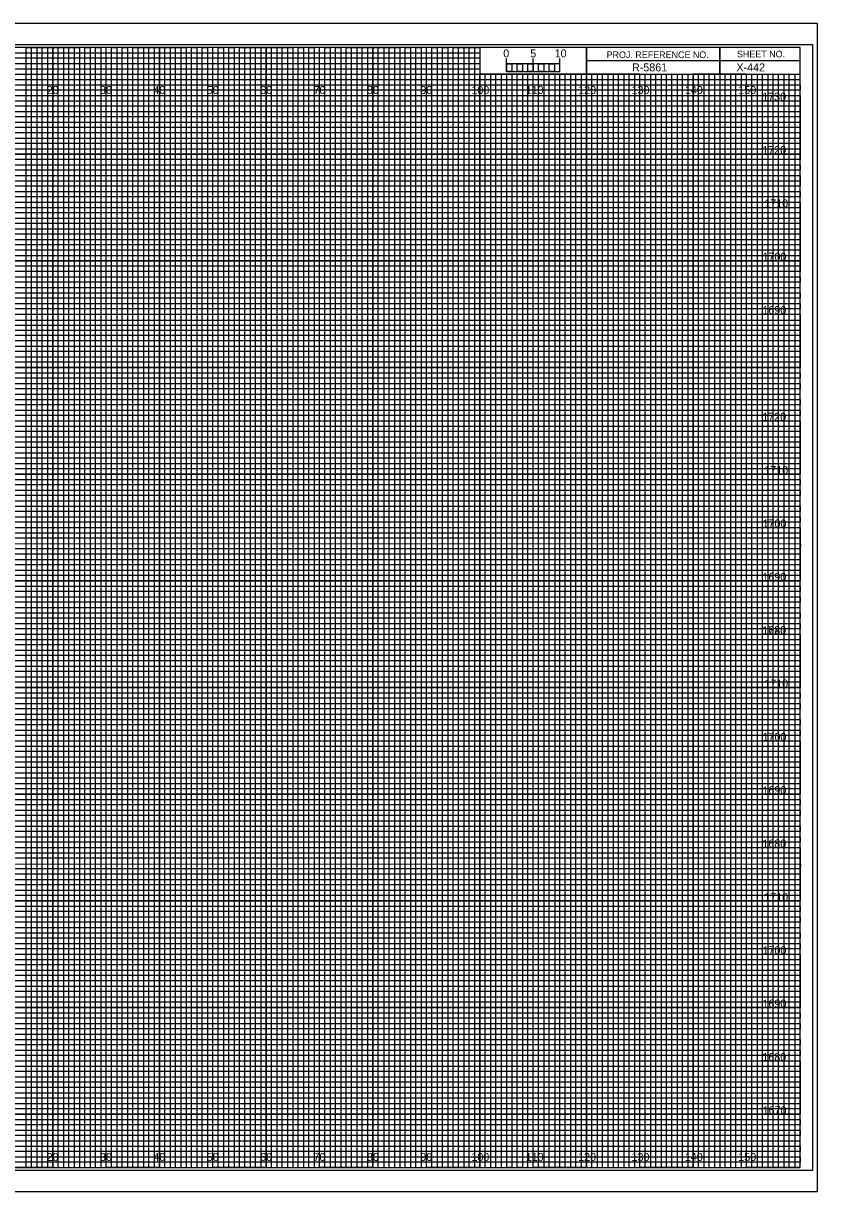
# Model space of a CAD drawing. Extents: x -13 to 323, y -5 to 1314.
# Drawn here: x 174.5 to 323.3, y 215.5 to 434.5 of the extents above; entities that cross this region are included whole.
import ezdxf

# ---------------------------------------------------------------- set-up
doc = ezdxf.new("R2010")
doc.units = 0
for name, color, linetype in [('Prop XS Bar Scale Labels', 7, 'Continuous'), ('Prop XS Project Number', 7, 'Continuous'), ('Prop XS Sheet Number', 7, 'Continuous'), ('Raster_Level_0', 7, 'Continuous'), ('Scratch_Level_3', 7, 'Continuous'), ('Sheet Cross Section CELL', 7, 'Continuous'), ('Sheet Cross Section Grid Major CELL', 7, 'Continuous'), ('Sheet Cross Section Grid Middle CELL', 7, 'Continuous'), ('Sheet Cross Section Grid Minor 1 CELL', 7, 'Continuous'), ('Sheet Cross Section Grid Minor 2 CELL', 7, 'Continuous'), ('Sheet Cross Section Scale CELL', 7, 'Continuous'), ('Sheet Cutting Line CELL', 7, 'Continuous'), ('Sheet DOT Grid CELL', 7, 'Continuous'), ('Sheet Plot Border Inside CELL', 7, 'Continuous'), ('Sheet Plot Border Outside CELL', 7, 'Continuous')]:
    doc.layers.add(name, color=color, linetype=linetype)

msp = doc.modelspace()

# ---------------------------------------------------------------- linework, layer by layer
at = {"layer": 'Sheet Cross Section CELL'}
for p, q in [((305, 430), (305, 425)), ((305, 425), (305, 430)), ((280, 427.5), (280, 425)), ((320, 427.49), (280, 427.49)), ((280, 425), (320, 425))]:
    msp.add_line(p, q, dxfattribs=at)
for points in [[(320, 430), (0, 430), (0, 220), (320, 220)], [(280, 430), (260, 430), (260, 425.03), (280, 425.03)], [(320, 430), (280, 430), (280, 425), (320, 425)]]:
    msp.add_lwpolyline(points, close=True, dxfattribs=at)
at = {"layer": 'Sheet Cross Section Grid Major CELL'}
for p, q in [((190, 430), (180, 430)), ((180, 430), (180, 220)), ((190, 220), (190, 430)), ((210, 430), (200, 430)), ((200, 430), (200, 220)), ((210, 220), (210, 430)), ((230, 430), (220, 430)), ((220, 430), (220, 220)), ((230, 220), (230, 430)), ((250, 430), (240, 430)), ((240, 430), (240, 220)), ((250, 220), (250, 430)), ((260, 430), (260, 220)), ((270, 220), (270, 425)), ((290, 425), (280, 425)), ((280, 425), (280, 220)), ((290, 220), (290, 425)), ((310, 425), (300, 425)), ((300, 425), (300, 220)), ((310, 220), (310, 425)), ((180, 220), (170, 220)), ((200, 220), (190, 220)), ((220, 220), (210, 220)), ((240, 220), (230, 220)), ((260, 220), (250, 220)), ((280, 220), (270, 220)), ((300, 220), (290, 220)), ((320, 220), (310, 220)), ((320, 220), (320, 220))]:
    msp.add_line(p, q, dxfattribs=at)
for points in [[(0, 420), (320, 420), (320, 410), (0, 410)], [(0, 400), (320, 400), (320, 390), (0, 390)], [(0, 380), (320, 380), (320, 370), (0, 370)], [(0, 360), (320, 360), (320, 350), (0, 350)], [(0, 340), (320, 340), (320, 330), (0, 330)], [(0, 320), (320, 320), (320, 310), (0, 310)], [(0, 300), (320, 300), (320, 290), (0, 290)], [(0, 280), (320, 280), (320, 270), (0, 270)], [(0, 260), (320, 260), (320, 250), (0, 250)], [(0, 240), (320, 240), (320, 230), (0, 230)]]:
    msp.add_lwpolyline(points, dxfattribs=at)
at = {"layer": 'Sheet Cross Section Grid Middle CELL'}
for points in [[(165, 220), (175, 220), (175, 430), (185, 430), (185, 220), (195, 220), (195, 430), (205, 430), (205, 220), (215, 220), (215, 430), (225, 430), (225, 220), (235, 220), (235, 430), (245, 430), (245, 220), (255, 220), (255, 430), (259.93, 430), (260, 430), (260, 425), (264.99, 425), (264.99, 220), (275, 220), (275, 425), (285, 425), (285, 220), (295, 220), (295, 425), (305, 425), (305, 220), (315, 220), (315, 425)], [(0, 425), (275, 425)], [(0, 405), (320, 405), (320, 415), (0, 415)], [(0, 385), (320, 385), (320, 395), (0, 395)], [(0, 365), (320, 365), (320, 375), (0, 375)], [(0, 345), (320, 345), (320, 355), (0, 355)], [(0, 325), (320, 325), (320, 335), (0, 335)], [(0, 305), (320, 305), (320, 315), (0, 315)], [(0, 285), (320, 285), (320, 295), (0, 295)], [(0, 265), (320, 265), (320, 275), (0, 275)], [(0, 245), (320, 245), (320, 255), (0, 255)], [(0, 225), (320, 225), (320, 235), (0, 235)]]:
    msp.add_lwpolyline(points, dxfattribs=at)
at = {"layer": 'Sheet Cross Section Grid Minor 1 CELL'}
for p, q in [((0, 429), (260, 429)), ((260, 427.98), (0, 427.98)), ((260, 429), (260, 427.98)), ((0, 427), (260, 427)), ((260, 425.89), (0, 425.89)), ((260, 427), (260, 425.89)), ((0, 424), (320, 424))]:
    msp.add_line(p, q, dxfattribs=at)
for points in [[(0, 423), (270, 423), (320, 423), (320, 422), (0, 422)], [(0, 421), (320, 421), (320, 419), (0, 419)], [(0, 418), (320, 418), (320, 417), (0, 416.98)], [(0, 416), (320, 416), (320, 414), (0, 414)], [(0, 413), (320, 413), (320, 412), (0, 412)], [(0, 411), (320, 411), (320, 409), (0, 409)], [(0, 408), (320, 408), (320, 407), (0, 407)], [(0, 406), (320, 406), (320, 404), (0, 404)], [(0, 403), (320, 403), (320, 402), (0, 402)], [(0, 401), (320, 401), (320, 399), (0, 399)], [(0, 398), (320, 398), (320, 397), (0, 397)], [(0, 396), (320, 396), (320, 393.95), (320, 393), (320, 392), (0, 392)], [(0, 394), (320, 394), (320, 393), (0, 393)], [(0, 391), (320, 391), (320, 389), (0, 389.03)], [(0, 389.03), (320, 389), (320, 388), (0, 388)], [(0, 387), (320, 387), (320, 386), (0, 386)], [(0, 384), (320, 384), (320, 383), (0, 383)], [(0, 382), (320, 382), (320, 381), (0, 381)], [(-0.07, 378.89), (320, 378.89), (320, 377.88), (-0.07, 377.88)], [(0, 377), (320, 377), (320, 376), (0, 376)], [(0, 374), (320, 374), (320, 373), (0, 373)], [(0, 372), (320, 372), (320, 371), (0, 371)], [(0, 369), (320, 369), (320, 368), (0, 368)], [(0, 367), (320, 367), (320, 366), (0, 366)], [(0, 364), (320, 364), (320, 363), (0, 363)], [(0, 362), (320, 362), (320, 361), (0, 361)], [(0, 359), (320, 359), (319.99, 357.98), (0, 358)], [(0, 357), (320, 357), (320, 356), (0, 356)], [(0, 354), (320, 354), (320, 353), (0, 353)], [(0, 352), (320, 352), (320, 351), (0, 351)], [(0, 349), (320, 349), (320, 348), (0, 348)], [(0, 347), (320, 347), (320, 346), (0, 346)], [(0, 344), (320, 344), (320, 343), (0, 343)], [(0, 342), (320, 342), (320, 341), (0, 341)], [(0, 339), (320, 339), (320, 338), (0, 338)], [(0, 336.99), (320.07, 336.91), (320, 336), (0, 336)], [(0, 334), (320, 334), (320, 333), (0, 333)], [(0, 332), (320, 332), (320, 331), (0, 331)], [(0, 329), (320, 329), (320, 328), (0, 328)], [(0, 327), (320, 327), (320, 326), (0, 326)], [(0, 324), (320, 324), (320, 323), (0, 323)], [(0, 322), (320, 322), (320, 321), (0, 321)], [(0, 319), (320, 319), (320, 318), (0, 318)], [(0, 317), (320, 317), (320, 316), (0, 316)], [(0, 314), (320, 314), (320, 313), (0, 313)], [(0, 312), (320, 312), (320, 311), (0, 311)], [(0, 309), (320, 309), (320, 308), (0, 308)], [(0, 307), (320, 307), (320, 306), (0, 306)], [(0, 304), (320, 304), (320, 303), (0, 303)], [(0, 302), (320, 302), (320, 301), (0, 301)], [(0, 299), (320, 299), (319.99, 297.98), (0, 298)], [(0, 297), (320, 297), (320, 296), (0, 296)], [(0, 294), (320, 294), (320, 293), (0, 293)], [(0, 292), (320, 292), (320, 291), (0, 291)], [(0, 289), (320, 289), (320, 288), (0, 288)], [(0, 287), (320, 287), (320, 286), (0, 286)], [(0, 284), (320, 284), (320, 283), (0, 283)], [(0, 282), (320, 282), (320, 281), (0, 281)], [(0, 279), (320, 279), (320, 278), (0, 278)], [(0, 276.99), (320.07, 276.91), (320, 276), (0, 276)], [(0, 274), (320, 274), (320, 273), (0, 273)], [(0, 272), (320, 272), (320, 271), (0, 271)], [(0, 269), (320, 269), (320, 268), (0, 268)], [(0, 267), (320, 267), (320, 266), (0, 266)], [(0, 264), (320, 264), (320, 263), (0, 263)], [(0, 262), (320, 262), (320, 261), (0, 261)], [(0, 259), (320, 259), (320, 258), (0, 258)], [(0, 257), (320, 257), (320, 256), (0, 256)], [(0, 254), (320, 254), (320, 253), (0, 253)], [(0, 252), (320, 252), (320, 251), (0, 251)], [(0, 249), (320, 249), (320, 248), (0, 248)], [(0, 247), (320, 247), (320, 246), (0, 246)], [(0, 244), (320, 244), (320, 243), (0, 243)], [(0, 242), (320, 242), (320, 241), (0, 241)], [(0, 239), (320, 239), (320, 238), (0, 238)], [(0, 237), (320, 237), (320, 236), (0, 236)], [(0, 234), (320, 234), (320, 233), (0, 233)], [(0, 232), (320, 232), (320, 231), (0, 231)], [(0, 229), (320, 229), (320, 228), (0, 228)], [(0, 227), (320, 227), (320, 226), (0, 226)], [(0, 224), (320, 224), (320, 223), (0, 223)], [(0, 222), (320, 222), (320, 221), (0, 221)]]:
    msp.add_lwpolyline(points, dxfattribs=at)
at = {"layer": 'Sheet Cross Section Grid Minor 2 CELL'}
for p, q in [((267, 425), (266.01, 425)), ((266.01, 425), (266.01, 220)), ((267, 220), (267, 425)), ((269, 425), (268, 425)), ((268, 425), (268, 220)), ((269, 220), (269, 425)), ((266.01, 220), (265, 220)), ((268, 220), (267, 220))]:
    msp.add_line(p, q, dxfattribs=at)
for points in [[(175, 220), (176, 220), (176, 430), (177, 430), (177, 220)], [(177, 220), (178, 220), (178, 430), (179, 430), (179, 220)], [(180, 220), (181, 220), (181, 430), (182, 430), (182, 220)], [(182, 220), (183, 220), (183, 430), (184, 430), (184, 220)], [(185, 220), (186, 220), (186, 430), (187, 430), (187, 220)], [(187, 220), (188, 220), (188, 430), (189, 430), (189, 220)], [(190, 220), (191, 220), (191, 430), (192, 430), (192, 220)], [(192, 220), (193, 220), (193, 430), (194, 430), (194, 220)], [(195, 220), (196, 220), (196, 430), (197, 430), (197, 220)], [(197, 220), (198, 220), (198, 430), (199, 430), (199, 220)], [(200, 220), (201, 220), (201, 430), (202, 430), (202, 220)], [(202, 220), (203, 220), (203, 430), (204, 430), (204, 220)], [(205, 220), (206, 220), (206, 430), (207, 430), (207, 220)], [(207, 220), (208, 220), (208, 430), (209, 430), (209, 220)], [(210, 220), (211, 220), (211, 430), (212, 430), (212, 220)], [(212, 220), (213, 220), (213, 430), (214, 430), (214, 220)], [(215, 220), (216, 220), (216, 430), (217, 430), (217, 220)], [(217, 220), (218, 220), (218, 430), (219, 430), (219, 220)], [(220, 220), (221, 220), (221, 430), (222, 430), (222, 220)], [(222, 220), (223, 220), (223, 430), (224, 430), (224, 220)], [(225, 220), (226, 220), (226, 430), (227, 430), (227, 220)], [(227, 220), (228, 220), (228, 430), (229, 430), (229, 220)], [(230, 220), (231, 220), (231, 430), (232, 430), (232, 220)], [(232, 220), (233, 220), (233, 430), (234, 430), (234, 220)], [(235, 220), (236, 220), (236, 430), (237, 430), (237, 220)], [(237, 220), (238, 220), (238, 430), (239, 430), (239, 220)], [(240, 220), (241, 220), (241, 430), (242, 430), (242, 220)], [(242, 220), (243, 220), (243, 430), (244, 430), (244, 220)], [(245, 220), (246, 220), (246, 430), (247, 430), (247, 220)], [(247, 220), (248, 220), (248, 430), (249, 430), (249, 220)], [(250, 220), (251, 220), (251, 430), (252, 430), (252, 220)], [(252, 220), (253, 220), (253, 430), (254, 430), (254, 220)], [(255, 220), (256, 220), (256, 430), (257, 430), (257, 220)], [(257, 220), (258, 220), (258, 430), (259, 430), (259, 220)], [(260, 220), (261, 220), (261, 425), (262.02, 425), (262.02, 220)], [(262, 220), (263, 220), (263, 425), (263.99, 425), (263.99, 220)], [(270, 220), (270.98, 220), (270.98, 425), (272, 425), (272, 220)], [(272, 220), (273, 220), (273, 425), (274.05, 425), (274.05, 220)], [(275, 220), (276, 220), (276, 425), (277, 425), (277, 220)], [(277, 220), (278, 220), (278, 425), (279, 425), (279, 220)], [(280, 220), (281, 220), (281, 425), (282, 425), (282, 220)], [(282, 220), (283, 220), (283, 425), (284, 425), (284, 220)], [(285, 220), (286, 220), (286, 425), (287, 425), (287, 220)], [(287, 220), (288, 220), (288, 425), (289, 425), (289, 220)], [(290, 220), (291, 220), (291, 425), (292, 425), (292, 220)], [(292, 220), (293, 220), (293, 425), (294, 425), (294, 220)], [(295, 220), (296, 220), (296, 425), (297, 425), (297, 220)], [(297, 220), (298, 220), (298, 425), (299, 425), (299, 220)], [(300, 220), (301, 220), (301, 425), (302, 425), (302, 220)], [(302, 220), (303, 220), (303, 425), (304, 425), (304, 220)], [(305, 220), (306, 220), (306, 425), (307, 425), (307, 220)], [(307, 220), (308, 220), (308, 425), (309, 425), (309, 220)], [(310, 220), (311, 220), (311, 425), (312, 425), (312, 220)], [(312, 220), (313, 220), (313, 425), (314, 425), (314, 220)], [(315, 220), (316, 220), (316, 425), (317, 425), (317, 220)], [(317, 220), (318, 220), (318, 425), (319, 425), (319, 220)]]:
    msp.add_lwpolyline(points, dxfattribs=at)
at = {"layer": 'Sheet Cross Section Scale CELL'}
for p, q in [((265, 425.49), (265, 427.9)), ((265, 426.9), (265, 427.9)), ((270, 425.49), (270, 427.9)), ((275, 425.49), (275, 427.9)), ((275, 426.9), (275, 427.9))]:
    msp.add_line(p, q, dxfattribs=at)
for points in [[(275, 426.9), (265, 426.9), (265, 425.49), (275, 425.49)], [(265, 426.9), (266, 426.9), (266, 425.49), (265, 425.49)], [(267, 426.9), (268, 426.9), (268, 425.49), (267, 425.49)], [(269, 426.9), (270, 426.9), (270, 425.49), (269, 425.49)], [(271, 426.9), (272, 426.9), (272, 425.49), (271, 425.49)], [(273, 426.9), (274, 426.9), (274, 425.49), (273, 425.49)]]:
    msp.add_lwpolyline(points, close=True, dxfattribs=at)
at = {"layer": 'Sheet Cutting Line CELL'}
for p, q in [((323.3, 434.5), (-13.4, 434.5)), ((-13.4, 215.5), (323.3, 215.5))]:
    msp.add_line(p, q, dxfattribs=at)
at = {"layer": 'Sheet DOT Grid CELL'}
for p, q in [((180, 220), (180, 430)), ((190, 220), (190, 430)), ((200, 220), (200, 430)), ((210, 220), (210, 430)), ((220, 220), (220, 430)), ((230, 220), (230, 430)), ((240, 220), (240, 430)), ((250, 220), (250, 430)), ((260, 220), (260, 424.69)), ((270, 220), (270, 424.69)), ((280, 220), (280, 424.69)), ((290, 220), (290, 424.69)), ((300, 220), (300, 424.69)), ((310, 220), (310, 424.69)), ((0, 420), (320, 420)), ((0, 410), (320, 410)), ((0, 400), (320, 400)), ((0, 390), (320, 390)), ((0, 380), (320, 380)), ((0, 370), (320, 370)), ((0, 360), (320, 360)), ((0, 350), (320, 350)), ((0, 340), (320, 340)), ((0, 330), (320, 330)), ((0, 320), (320, 320)), ((0, 310), (320, 310)), ((0, 300), (320, 300)), ((0, 290), (320, 290)), ((0, 280), (320, 280)), ((0, 270), (320, 270)), ((0, 260), (320, 260)), ((0, 250), (320, 250)), ((0, 240), (320, 240)), ((0, 230), (320, 230))]:
    msp.add_line(p, q, dxfattribs=at)
at = {"layer": 'Sheet Plot Border Inside CELL'}
msp.add_lwpolyline([(-10.8, 219.5), (322.4, 219.5), (322.4, 430.5), (-10.8, 430.5)], close=True, dxfattribs=at)
at = {"layer": 'Sheet Plot Border Outside CELL'}
msp.add_lwpolyline([(-13.4, 215.5), (323.3, 215.5), (323.3, 434.5), (-13.4, 434.5)], close=True, dxfattribs=at)

# ---------------------------------------------------------------- texts
at = {"layer": 'Prop XS Bar Scale Labels'}
for s, p in [('5', (269.47, 428.12)), ('10', (274.04, 428.12))]:
    msp.add_text(s, height=1.5, dxfattribs=at).set_placement(p)
at = {"layer": 'Prop XS Project Number'}
msp.add_text('R-5861', height=1.5, dxfattribs=at).set_placement((288.53, 425.5))
at = {"layer": 'Prop XS Sheet Number'}
msp.add_text('X-442', height=1.5, dxfattribs=at).set_placement((308.09, 425.5))
at = {"layer": 'Raster_Level_0'}
for s, p in [('20', (178.86, 421.25)), ('30', (188.86, 421.25)), ('40', (198.86, 421.25)), ('50', (208.86, 421.25)), ('60', (218.86, 421.25)), ('70', (228.86, 421.25)), ('80', (238.86, 421.25)), ('90', (248.86, 421.25)), ('100', (258.44, 421.25)), ('110', (268.62, 421.25)), ('120', (278.44, 421.25)), ('130', (288.44, 421.25)), ('140', (298.44, 421.25)), ('150', (308.44, 421.25)), ('20', (178.86, 221.25)), ('30', (188.86, 221.25)), ('40', (198.86, 221.25)), ('50', (208.86, 221.25)), ('60', (218.86, 221.25)), ('70', (228.86, 221.25)), ('80', (238.86, 221.25)), ('90', (248.86, 221.25)), ('100', (258.44, 221.25)), ('110', (268.62, 221.25)), ('120', (278.44, 221.25)), ('130', (288.44, 221.25)), ('140', (298.44, 221.25)), ('150', (308.44, 221.25))]:
    msp.add_text(s, height=1.5, dxfattribs=at).set_placement(p)
at = {"layer": 'Scratch_Level_3'}
for s, p in [('1730', (312.92, 420)), ('1720', (312.93, 410)), ('1710', (313.31, 400)), ('1700', (312.98, 390)), ('1690', (312.97, 380)), ('1720', (312.93, 360)), ('1710', (313.31, 350)), ('1700', (312.98, 340)), ('1690', (312.97, 330)), ('1720', (312.93, 320)), ('1680', (312.95, 320)), ('1710', (313.31, 310)), ('1700', (312.98, 300)), ('1690', (312.97, 290)), ('1680', (312.95, 280)), ('1710', (313.31, 270)), ('1700', (312.98, 260)), ('1690', (312.97, 250)), ('1680', (312.95, 240)), ('1670', (313, 230))]:
    msp.add_text(s, height=1.5, dxfattribs=at).set_placement(p)
at = {"layer": 'Sheet Cross Section CELL'}
for s, p in [('PROJ. REFERENCE NO.', (283.77, 427.99)), ('SHEET NO.', (308.19, 428.12))]:
    msp.add_text(s, height=1.25, dxfattribs=at).set_placement(p)
at = {"layer": 'Sheet Cross Section Scale CELL'}
msp.add_text('0', height=1.5, dxfattribs=at).set_placement((264.41, 428.12))

doc.saveas('drawing.dxf')
